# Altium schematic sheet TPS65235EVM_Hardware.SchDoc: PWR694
size 431 x 279 mm; Date: Not shown in title block; ApprovedBy: Not shown in title block; CheckedBy: Not shown in title block; Author: Not shown in title block; CompanyName: Not shown in title block; DrawnBy: Junjie Mai; Engineer: Junjie Mai; Organization: Not shown in title block; Address1: Not shown in title block; Address2: Not shown in title block; Address3: Not shown in title block; Address4: Not shown in title block; DocumentNumber: 1; Revision: Use project parameter SCH_Rev; SheetNumber: 2; SheetTotal: 2; PageSetup: Record=PageOptions¦CenterHorizontal=True¦CenterVertical=True¦PrintScale=1.00¦XCorrection=1.00¦YCorrection=1.00¦PrintKind=0¦BorderSize=5000000¦LeftOffset=0¦BottomOffset=0¦Orientation=2¦PaperLength=1000¦PaperWidth=1000¦Scale=100¦PaperSource=15¦PrintQuality=-3¦MediaType=1¦DitherType=10¦PrintScaleMode=1¦PaperKind=A1 (594 x 841mm)¦PaperIndex=124
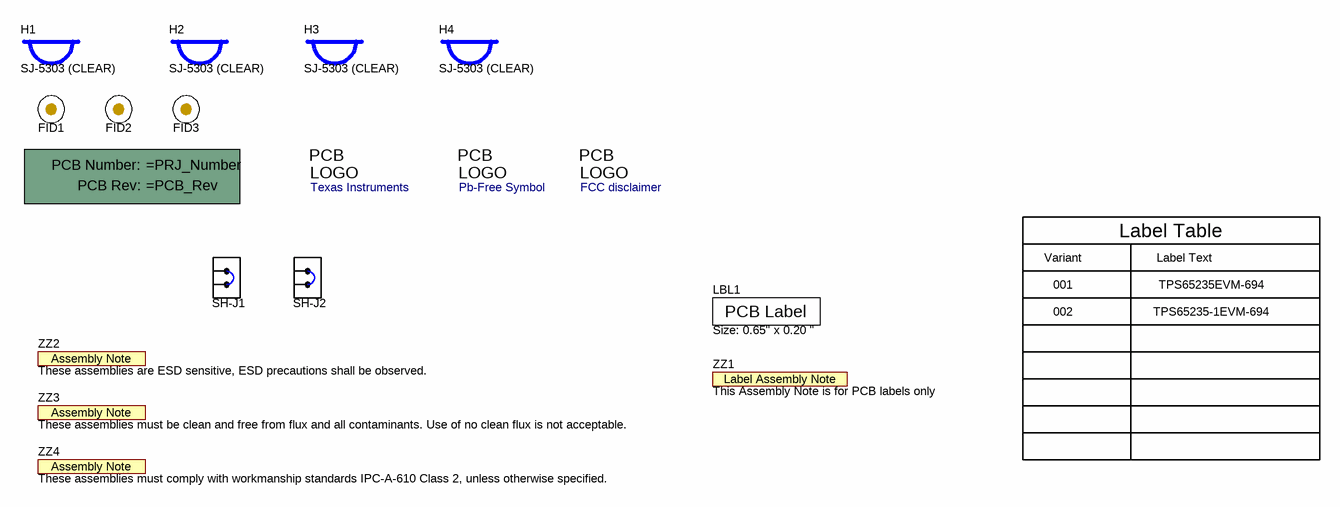
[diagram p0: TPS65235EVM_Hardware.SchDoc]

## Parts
!PCB  Printed Circuit Board  (value not drawn)  (mechanical)
FID1  Fiducial  [Fiducial10-20]  (value not drawn)
FID2  Fiducial  [Fiducial10-20]  (value not drawn)
FID3  Fiducial  [Fiducial10-20]  (value not drawn)
H1  SJ-5303 (CLEAR)  [Bumpon_SJ5003Transparent]
H2  SJ-5303 (CLEAR)  [Bumpon_SJ5003Transparent]
H3  SJ-5303 (CLEAR)  [Bumpon_SJ5003Transparent]
H4  SJ-5303 (CLEAR)  [Bumpon_SJ5003Transparent]
LBL1  Size: 0.65" x 0.20 "  [Label_650x200]
Logo1  Texas Instruments  [TI_Stacked_Overlay_Small]  (no BOM)
Logo2  Pb-Free Symbol  [Pb-Free_Overlay_Small]  (no BOM)
Logo3  FCC disclaimer  [FCC_disclaimer]  (no BOM)
SH-J1  969102-0000-DA  [SNT-100-BK-G]  (value not drawn)
SH-J2  969102-0000-DA  [SNT-100-BK-G]  (value not drawn)
ZZ1  This Assembly Note is for PCB labels only  [AssemblyNoteLabel]  (no BOM)
ZZ2  These assemblies are ESD sensitive, ESD precautions shall be observed.  [AssemblyNote]  (no BOM)
ZZ3  These assemblies must be clean and free from flux and all contaminants. Use of no clean flux is not acceptable.  [AssemblyNote]  (no BOM)
ZZ4  These assemblies must comply with workmanship standards IPC-A-610 Class 2, unless otherwise specified.  [AssemblyNote]  (no BOM)

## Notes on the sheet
- Variant
- 001
- Label Table
- Label Text
- TPS65235EVM-694
- 002
- TPS65235-1EVM-694

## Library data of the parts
!PCB = PCB: Manufacturer: Any; SymbolCreator: a0412235
FID1-FID3 = Fiducial: Fiducial mark.  There is nothing to buy or mount.; SymbolCreator: codlsc
H1-H4 = SJ-5303 (CLEAR): Bumpon, Hemisphere, 0.44 X 0.20, Clear; Manufacturer: 3M; SymbolCreator: a0412235
LBL1 = THT-14-423-10: Thermal Transfer Printable Labels, 0.650" W x 0.200" H - 10,000 per roll; Manufacturer: Brady; SymbolCreator: a0412235; CompType: Label
Logo1 = TI_Logo: Texas Instrument Corporate Signature; SymbolCreator: a0412235
Logo2 = Pb-Free: SymbolCreator: a0412235
Logo3 = FCC_disclaimer: SymbolCreator: codlsc
SH-J1 SH-J2 = 969102-0000-DA: Shunt, 100mil, Gold plated, Black; Manufacturer: 3M; Alternate Manufacturer: Samtec; Value: 1x2; Note: You can "mate" this to a header by matching the designator.  i.e. use SH-J3 for header J3
ZZ1 = AssemblyNoteLabel: SymbolCreator: a0412235
ZZ2-ZZ4 = AssemblyNote: SymbolCreator: codlsc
